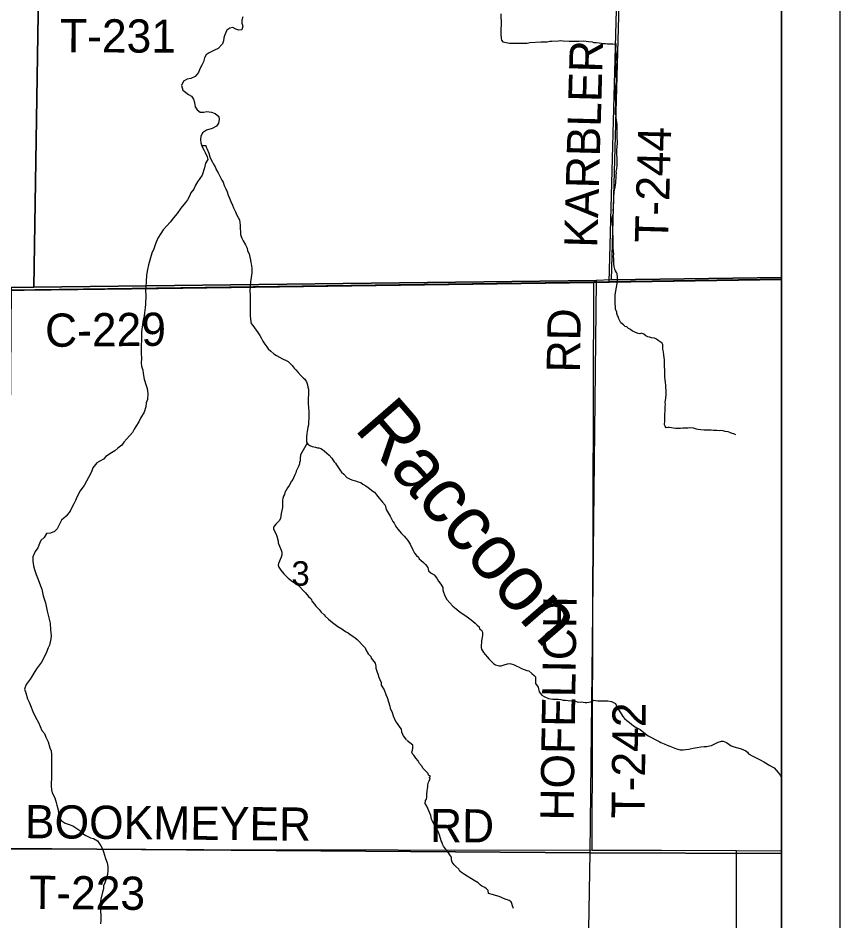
# Model space of a CAD drawing. Extents: x 36.7 to 70.7, y 0 to 22.
# Drawn here: x 44.287 to 45.693, y 18.785 to 20.33 of the extents above; entities that cross this region are included whole.
import ezdxf

# ---------------------------------------------------------------- set-up
doc = ezdxf.new("R2010")
doc.units = 0
for name, color, linetype in [('Default', 7, 'Continuous'), ('GM_X_County_Road', 7, 'Continuous'), ('GM_X_County_Road_Text', 7, 'Continuous'), ('GM_X_Minor_River', 7, 'Continuous'), ('GM_X_Minor_River_Text', 7, 'Continuous'), ('GM_X_Section', 7, 'Continuous'), ('GM_X_Section_Text', 7, 'Continuous'), ('GM_X_Township_Road', 7, 'Continuous'), ('GM_X_Township_Road_Text', 7, 'Continuous'), ('SH_Data', 7, 'Continuous')]:
    doc.layers.add(name, color=color, linetype=linetype)

msp = doc.modelspace()

# ---------------------------------------------------------------- linework, layer by layer
at = {"layer": 'Default'}
for points in [[(45.5934, 19.886), (45.5934, 20.8905), (45.3296, 20.8874), (45.3017, 19.8821)], [(45.5934, 18.9006), (45.5934, 19.886), (45.3017, 19.8821), (45.2759, 19.881), (45.2652, 18.9013)], [(45.5934, 17.918), (45.5934, 18.9006), (45.2652, 18.9013), (45.2484, 17.9213)]]:
    msp.add_lwpolyline(points, close=True, dxfattribs=at)
at = {"layer": 'GM_X_County_Road'}
for p, q in [((45.2983, 19.8779), (45.5934, 19.8826)), ((44.0658, 19.8612), (44.5269, 19.8674))]:
    msp.add_line(p, q, dxfattribs=at)
msp.add_lwpolyline([(44.5269, 19.8674), (45.2724, 19.8775), (45.2983, 19.8779)], dxfattribs=at)
at = {"layer": 'GM_X_Minor_River'}
for points in [[(45.1132, 20.3374), (45.1133, 20.3184), (45.113, 20.3112), (45.113, 20.302), (45.1138, 20.2956), (45.1142, 20.2922), (45.1165, 20.2895), (45.1279, 20.2873), (45.1336, 20.2873), (45.1458, 20.287), (45.1583, 20.2871), (45.1628, 20.2882), (45.1814, 20.2894), (45.1867, 20.2891), (45.1921, 20.2891), (45.1966, 20.2903), (45.2004, 20.2907), (45.2114, 20.2911), (45.2148, 20.2915), (45.2194, 20.2911), (45.23, 20.2904), (45.2463, 20.2905), (45.2547, 20.2909), (45.2589, 20.2906), (45.263, 20.2898), (45.2691, 20.2891), (45.2722, 20.2884), (45.276, 20.288), (45.2813, 20.2876), (45.2847, 20.2873), (45.2885, 20.2865), (45.2923, 20.2866)], [(44.6714, 20.332), (44.6694, 20.3264), (44.6694, 20.3211), (44.6712, 20.3161), (44.6696, 20.31), (44.6647, 20.3093), (44.6594, 20.3113), (44.6541, 20.314), (44.6492, 20.3125), (44.6442, 20.3096), (44.6403, 20.3013), (44.6387, 20.296), (44.6383, 20.291), (44.6364, 20.2857), (44.6294, 20.2782), (44.6226, 20.2752), (44.6138, 20.2704), (44.6084, 20.267), (44.6057, 20.2618), (44.6038, 20.2553), (44.601, 20.2493), (44.5979, 20.2429), (44.5956, 20.2368), (44.5898, 20.23), (44.5822, 20.2267), (44.5761, 20.2253), (44.5696, 20.2219), (44.5665, 20.2144), (44.5687, 20.2067), (44.5781, 20.199), (44.5834, 20.1963), (44.5871, 20.191), (44.5889, 20.1856), (44.59, 20.178), (44.593, 20.1731), (44.5986, 20.1692), (44.6047, 20.1691), (44.61, 20.1699), (44.6176, 20.169), (44.624, 20.167), (44.63, 20.1617), (44.6307, 20.1567), (44.6295, 20.1499), (44.626, 20.145), (44.6188, 20.1409), (44.6093, 20.138), (44.6024, 20.1335), (44.5993, 20.1274), (44.5988, 20.1221), (44.5995, 20.1164), (44.6017, 20.1096), (44.6047, 20.1046), (44.6069, 20.0997), (44.6103, 20.0928), (44.6113, 20.0878), (44.6075, 20.0818), (44.6055, 20.0735), (44.6015, 20.0614), (44.5977, 20.0553), (44.5938, 20.0497), (44.5904, 20.044), (44.5872, 20.0372), (44.5826, 20.0308), (44.5803, 20.0252), (44.5764, 20.0191), (44.5733, 20.0142), (44.5652, 20.0048), (44.5587, 19.9954), (44.5525, 19.9879), (44.5471, 19.9807), (44.541, 19.9743), (44.5352, 19.9679), (44.531, 19.9615)], [(45.2923, 20.2866), (45.2957, 20.2862), (45.3003, 20.2862), (45.3044, 20.2859), (45.3103, 20.2854)], [(45.3069, 19.9048), (45.3066, 19.9098), (45.3062, 19.9143), (45.3063, 19.9177), (45.3056, 19.9227), (45.3063, 19.9261), (45.3053, 19.9364), (45.3054, 19.9512), (45.3051, 19.9569), (45.3047, 19.9599), (45.3048, 19.9724), (45.3041, 19.9777), (45.3034, 19.9816), (45.3038, 19.9869), (45.3046, 19.9929), (45.3058, 19.9963), (45.3055, 20.002), (45.3059, 20.0047), (45.3059, 20.01), (45.3063, 20.0134), (45.3064, 20.0218), (45.3072, 20.0332), (45.3084, 20.0407), (45.3092, 20.0449), (45.3096, 20.0479), (45.3097, 20.051), (45.3101, 20.0567), (45.3105, 20.0616), (45.3109, 20.0646), (45.3102, 20.0677), (45.3114, 20.0722), (45.3118, 20.0775), (45.3118, 20.0825), (45.3122, 20.0855), (45.3119, 20.0916), (45.3115, 20.0954), (45.3116, 20.0984), (45.3116, 20.1037), (45.312, 20.1102), (45.3125, 20.1155), (45.3125, 20.1201), (45.3118, 20.1246), (45.3122, 20.1314), (45.3119, 20.1364), (45.3123, 20.1413), (45.312, 20.144), (45.312, 20.1478), (45.3113, 20.1527), (45.3109, 20.1558), (45.3098, 20.1596), (45.3102, 20.1626), (45.3095, 20.1653), (45.3095, 20.171), (45.3096, 20.1854), (45.3093, 20.1926), (45.3094, 20.2002), (45.309, 20.2048), (45.3091, 20.2089), (45.3107, 20.2211), (45.3107, 20.2268), (45.3104, 20.2298), (45.3105, 20.237), (45.3101, 20.2427), (45.3102, 20.2465), (45.3106, 20.2503), (45.3098, 20.2552), (45.3103, 20.2583), (45.3107, 20.2621), (45.3107, 20.2689), (45.3104, 20.2723), (45.31, 20.2765), (45.3101, 20.283), (45.3105, 20.2864)], [(44.6009, 20.1121), (44.608, 20.112), (44.6088, 20.1089), (44.6103, 20.1059), (44.613, 20.0991), (44.6149, 20.0926), (44.6172, 20.0873), (44.6195, 20.0835), (44.621, 20.0801), (44.6241, 20.0752), (44.6264, 20.0699), (44.6291, 20.065), (44.6314, 20.0608), (44.6333, 20.057), (44.6356, 20.0528), (44.6375, 20.049), (44.6395, 20.0437), (44.6421, 20.0377), (44.6444, 20.0327), (44.6464, 20.027), (44.6487, 20.0217), (44.651, 20.0161), (44.6537, 20.01), (44.6556, 20.0051), (44.6571, 20.0017), (44.659, 19.9982), (44.6613, 19.9929), (44.6636, 19.9888), (44.6656, 19.9846), (44.6663, 19.98), (44.6668, 19.9755), (44.6668, 19.9694), (44.6672, 19.9649), (44.6676, 19.9595), (44.6684, 19.9565), (44.6695, 19.9531), (44.6722, 19.9489), (44.676, 19.9421), (44.6787, 19.9364), (44.6791, 19.9319), (44.6822, 19.9266), (44.6826, 19.9239), (44.6837, 19.9186), (44.6853, 19.9121), (44.6857, 19.9091), (44.6861, 19.9064), (44.6865, 19.9011), (44.6869, 19.8985), (44.6869, 19.8943), (44.6858, 19.8863), (44.6847, 19.8787), (44.684, 19.8703), (44.6836, 19.8639), (44.6841, 19.8551), (44.6837, 19.8513), (44.6837, 19.8479), (44.6841, 19.843), (44.6841, 19.8396), (44.6838, 19.8289), (44.6839, 19.8206), (44.685, 19.8103), (44.6854, 19.8073), (44.6885, 19.8039), (44.6916, 19.7997), (44.6969, 19.7921), (44.7003, 19.7868), (44.7026, 19.7827), (44.7053, 19.7774), (44.7088, 19.7721), (44.7122, 19.7675), (44.7149, 19.7641), (44.7191, 19.76), (44.7244, 19.7554), (44.729, 19.7524), (44.7343, 19.7498), (44.7393, 19.7471), (44.7454, 19.7441), (44.7488, 19.7423), (44.7526, 19.7389), (44.7556, 19.7354), (44.7591, 19.7309), (44.7621, 19.7279), (44.766, 19.7237), (44.7705, 19.7184), (44.7744, 19.7146), (44.7774, 19.712), (44.7801, 19.7078), (44.782, 19.7025), (44.7824, 19.6983), (44.7836, 19.6949), (44.7836, 19.6858), (44.7829, 19.6794), (44.7829, 19.6748), (44.7833, 19.6702), (44.7837, 19.6638), (44.7841, 19.657), (44.7842, 19.644), (44.7838, 19.6395), (44.7835, 19.6368), (44.7835, 19.6342), (44.7828, 19.63)], [(44.531, 19.9615), (44.526, 19.9532), (44.5217, 19.9438), (44.5189, 19.9351), (44.5154, 19.9279), (44.5134, 19.9196), (44.5099, 19.9075), (44.5079, 19.8995), (44.5067, 19.89), (44.5058, 19.8794), (44.5053, 19.8699), (44.5048, 19.862), (44.5051, 19.857), (44.5051, 19.8506), (44.5046, 19.8457), (44.5046, 19.8396), (44.5041, 19.8346), (44.5029, 19.8256), (44.5025, 19.8206), (44.5016, 19.8157), (44.5004, 19.8108), (44.4996, 19.8043), (44.4984, 19.7983), (44.4979, 19.7918), (44.4975, 19.7565), (44.4978, 19.7474), (44.4974, 19.7402), (44.4981, 19.7345), (44.4999, 19.7273), (44.5009, 19.7216), (44.5027, 19.712), (44.506, 19.701), (44.5075, 19.6961), (44.5085, 19.6873), (44.508, 19.6771), (44.5061, 19.6714), (44.5052, 19.665), (44.5025, 19.6559), (44.4963, 19.6453), (44.4932, 19.6393), (44.4882, 19.6313), (44.4854, 19.6264), (44.4823, 19.6208), (44.4727, 19.6099), (44.4677, 19.6042), (44.4643, 19.599), (44.4574, 19.5941), (44.452, 19.5892), (44.4467, 19.5859), (44.4371, 19.5799), (44.4329, 19.575), (44.4268, 19.572), (44.4214, 19.5687), (44.4145, 19.5604), (44.4126, 19.5551), (44.4106, 19.5502), (44.404, 19.5377), (44.3997, 19.5302), (44.3921, 19.5204), (44.3901, 19.5151), (44.3874, 19.5102), (44.385, 19.5045), (44.3819, 19.4985), (44.3785, 19.4924), (44.3757, 19.4864), (44.3692, 19.4774), (44.3611, 19.4706), (44.3565, 19.4619), (44.3538, 19.4559), (44.3488, 19.4514), (44.3419, 19.4488), (44.3355, 19.4481), (44.3312, 19.4413), (44.3258, 19.4361), (44.3235, 19.4308), (44.3204, 19.4236), (44.3158, 19.4172), (44.3119, 19.4081), (44.3118, 19.4005), (44.3128, 19.3926), (44.315, 19.3865), (44.3176, 19.3781), (44.3209, 19.3693), (44.3253, 19.3586), (44.3272, 19.3525), (44.3297, 19.3415), (44.3333, 19.3293), (44.3362, 19.3152), (44.3391, 19.3038), (44.3413, 19.2943), (44.3423, 19.2833), (44.3433, 19.273), (44.3425, 19.2677), (44.3405, 19.2571), (44.3382, 19.2522), (44.3354, 19.2447), (44.3323, 19.2386), (44.3265, 19.2277), (44.318, 19.2164), (44.3138, 19.2088), (44.3103, 19.2035)], [(45.515, 19.6171), (45.5116, 19.6183), (45.5089, 19.619), (45.5048, 19.621), (45.5021, 19.6218), (45.4968, 19.6226), (45.4934, 19.6237), (45.4896, 19.6245), (45.4866, 19.6234), (45.4828, 19.6242), (45.4768, 19.6243), (45.473, 19.6247), (45.4684, 19.6251), (45.4608, 19.6248), (45.4555, 19.6252), (45.4506, 19.626), (45.4479, 19.6264), (45.443, 19.628), (45.4373, 19.6288), (45.4328, 19.6284), (45.4301, 19.6281), (45.4244, 19.6281), (45.4207, 19.6278), (45.4161, 19.6275), (45.4127, 19.6279), (45.4081, 19.6283), (45.4051, 19.6287), (45.4013, 19.6291), (45.3987, 19.6291), (45.396, 19.6288), (45.3941, 19.6314), (45.393, 19.6341), (45.3935, 19.6409), (45.3935, 19.6497), (45.3944, 19.6603), (45.3944, 19.6656), (45.3948, 19.6686), (45.3945, 19.6721), (45.3953, 19.6797), (45.3957, 19.6861), (45.3958, 19.6895), (45.3958, 19.6933), (45.3954, 19.6971), (45.3955, 19.7021), (45.3948, 19.7062), (45.394, 19.7116), (45.3937, 19.7154), (45.3934, 19.7199), (45.3934, 19.729), (45.3931, 19.7321), (45.3932, 19.7454), (45.3921, 19.753), (45.3914, 19.759), (45.3903, 19.7632), (45.3903, 19.7674), (45.39, 19.7708), (45.3889, 19.7735), (45.3855, 19.7762), (45.3825, 19.7781), (45.3795, 19.7804), (45.3761, 19.7823), (45.3708, 19.7831), (45.3677, 19.7839), (45.3643, 19.7843), (45.3609, 19.7863), (45.3575, 19.789), (45.3538, 19.7909), (45.3507, 19.7898), (45.3481, 19.7902), (45.3435, 19.7917), (45.3409, 19.7929), (45.3382, 19.7944), (45.3348, 19.7971), (45.3314, 19.7987), (45.3284, 19.8014), (45.3258, 19.8025), (45.3232, 19.8052), (45.3186, 19.8087), (45.3164, 19.8117), (45.3149, 19.8155), (45.3142, 19.8182), (45.3127, 19.8212), (45.3116, 19.8243), (45.3116, 19.8269), (45.3093, 19.8319), (45.309, 19.8365), (45.3087, 19.8403), (45.3087, 19.8456), (45.3084, 19.852), (45.3088, 19.8566), (45.3092, 19.8592), (45.3104, 19.8664), (45.3116, 19.8721), (45.312, 19.8763), (45.3124, 19.8816), (45.3125, 19.8873), (45.3121, 19.8922), (45.311, 19.8949), (45.3095, 19.8976), (45.308, 19.9006), (45.3069, 19.9048)], [(44.7828, 19.63), (44.7813, 19.6224), (44.7809, 19.6189), (44.7802, 19.6129), (44.7802, 19.6068), (44.7806, 19.6041), (44.7825, 19.6007), (44.7863, 19.5988), (44.7898, 19.597), (44.7958, 19.5958), (44.7989, 19.5947), (44.8015, 19.5944), (44.8046, 19.5932), (44.8076, 19.5917), (44.8107, 19.5895), (44.8152, 19.5853), (44.8194, 19.5819), (44.8236, 19.577), (44.8255, 19.5743), (44.8278, 19.5709), (44.8298, 19.5683), (44.8317, 19.5653), (44.8386, 19.5554), (44.8405, 19.5528), (44.8443, 19.5494), (44.8496, 19.5441), (44.8549, 19.541), (44.8599, 19.5392), (44.8641, 19.5381), (44.869, 19.5366), (44.8732, 19.5351), (44.877, 19.5324), (44.8816, 19.5298), (44.8861, 19.5268), (44.8938, 19.5207), (44.8968, 19.5185), (44.9003, 19.5143), (44.9048, 19.5082), (44.9102, 19.5014), (44.9148, 19.4965), (44.9167, 19.4889), (44.9236, 19.4776), (44.9282, 19.4688), (44.9305, 19.4658), (44.932, 19.4624), (44.9343, 19.4582), (44.937, 19.4548), (44.9397, 19.4518), (44.9431, 19.448), (44.9473, 19.4435), (44.9507, 19.4397), (44.9538, 19.4359), (44.958, 19.4299), (44.9626, 19.42), (44.9653, 19.4143), (44.9687, 19.4102), (44.9718, 19.4075), (44.9729, 19.4045), (44.976, 19.4022), (44.9806, 19.3981), (44.984, 19.3947), (44.9882, 19.3897), (44.9894, 19.384), (44.9939, 19.3803), (44.9989, 19.3773), (45.0012, 19.3746), (45.0038, 19.3704), (45.0061, 19.3667), (45.0103, 19.3614), (45.0134, 19.3553), (45.0134, 19.3515), (45.0146, 19.3477), (45.0165, 19.3428), (45.0181, 19.339), (45.0204, 19.3348), (45.0257, 19.3295), (45.031, 19.3238), (45.0364, 19.3189), (45.0436, 19.3133), (45.0531, 19.3069), (45.0623, 19.3001), (45.0688, 19.2948), (45.0726, 19.291), (45.0756, 19.2884), (45.0764, 19.2849), (45.0798, 19.2827), (45.0817, 19.2793), (45.0814, 19.2732), (45.0807, 19.2679), (45.0799, 19.2637), (45.0796, 19.261), (45.0792, 19.2576), (45.0792, 19.253), (45.08, 19.25), (45.0831, 19.2443), (45.0861, 19.2409), (45.0899, 19.2364), (45.0926, 19.2334), (45.096, 19.23), (45.1006, 19.2258), (45.104, 19.2235)], [(44.7815, 19.6025), (44.7701, 19.5825), (44.7696, 19.5761), (44.7692, 19.5723), (44.7684, 19.5697), (44.7683, 19.567), (44.7667, 19.5629), (44.7624, 19.5546), (44.7619, 19.5519), (44.7603, 19.5482), (44.7571, 19.5403), (44.7548, 19.5377), (44.7509, 19.5302), (44.7478, 19.5264), (44.7458, 19.5219), (44.7434, 19.5182), (44.7426, 19.5148), (44.741, 19.5118), (44.7398, 19.508), (44.7394, 19.5054), (44.7392, 19.4989), (44.7395, 19.4951), (44.7391, 19.4925), (44.7383, 19.4876), (44.737, 19.4823), (44.7357, 19.4739), (44.7337, 19.4698), (44.7306, 19.4668), (44.7279, 19.4642), (44.7256, 19.4613), (44.724, 19.4586), (44.7236, 19.4552), (44.7276, 19.4479), (44.7298, 19.4433), (44.7319, 19.4349), (44.7318, 19.4323), (44.7343, 19.4262), (44.7368, 19.4197), (44.7379, 19.4159), (44.7382, 19.4113), (44.737, 19.4075), (44.735, 19.4034), (44.7342, 19.4008), (44.7326, 19.3966), (44.7321, 19.394), (44.7328, 19.3902), (44.7365, 19.3852), (44.7417, 19.379), (44.7487, 19.3716), (44.7565, 19.3658), (44.7655, 19.3603), (44.7788, 19.3464), (44.784, 19.3402), (44.7885, 19.336), (44.7903, 19.3314), (44.7943, 19.3271), (44.7965, 19.3237), (44.8021, 19.3178), (44.8054, 19.3136), (44.8106, 19.309), (44.8121, 19.3063), (44.818, 19.3012), (44.8247, 19.2958), (44.8337, 19.2891), (44.8408, 19.2848), (44.8453, 19.2817), (44.8483, 19.2798), (44.8516, 19.2778), (44.8553, 19.2751), (44.8598, 19.2723), (44.8639, 19.2692), (44.8673, 19.2665), (44.8706, 19.263), (44.8762, 19.2568), (44.8806, 19.2522), (44.8817, 19.2491), (44.8861, 19.2422), (44.8905, 19.2376), (44.8912, 19.2349), (44.8979, 19.226), (44.8986, 19.2234), (44.8989, 19.2207), (44.8988, 19.2177), (44.9006, 19.2123), (44.9031, 19.2062), (44.9035, 19.2035), (44.9082, 19.1932), (44.9084, 19.1886), (44.9132, 19.1802), (44.9164, 19.1726), (44.9186, 19.1672), (44.9232, 19.1523), (44.9235, 19.1489), (44.9268, 19.1416), (44.9289, 19.1359), (44.9318, 19.129), (44.934, 19.1252), (44.9369, 19.1209), (44.9399, 19.1159), (44.9421, 19.1129), (44.9427, 19.1087)], [(45.104, 19.2235), (45.1078, 19.222), (45.1105, 19.2213), (45.1135, 19.2217), (45.1188, 19.2232), (45.1245, 19.2252), (45.1279, 19.2255), (45.1306, 19.2248), (45.1348, 19.2237), (45.1394, 19.2218), (45.1443, 19.2192), (45.1485, 19.2169), (45.1576, 19.2135), (45.161, 19.2128), (45.166, 19.2086), (45.1698, 19.2052), (45.1721, 19.2026), (45.1725, 19.195), (45.1725, 19.1912), (45.1767, 19.1848), (45.1783, 19.1768), (45.1829, 19.1715), (45.1871, 19.1689), (45.1943, 19.1658), (45.2019, 19.1644), (45.211, 19.1644), (45.2159, 19.1641), (45.2197, 19.1629), (45.2235, 19.1626), (45.2281, 19.1622), (45.2338, 19.1615), (45.2372, 19.1611), (45.241, 19.1608), (45.2437, 19.16), (45.2467, 19.1596), (45.2505, 19.1597), (45.2539, 19.1593), (45.2573, 19.1586), (45.26, 19.1586), (45.2638, 19.1593), (45.2668, 19.1601), (45.2695, 19.1609)], [(44.3103, 19.2035), (44.3072, 19.1986), (44.3003, 19.1896), (44.2979, 19.1817), (44.2997, 19.1752), (44.3026, 19.1649), (44.3056, 19.1596), (44.3078, 19.1535), (44.3119, 19.1436), (44.3167, 19.1336), (44.3215, 19.1245), (44.3245, 19.1176), (44.3271, 19.1111), (44.3319, 19.1058), (44.3341, 19.0997), (44.3382, 19.0913), (44.3411, 19.081), (44.343, 19.076), (44.3437, 19.0696), (44.344, 19.0639), (44.3438, 19.0464), (44.3441, 19.0388), (44.3436, 19.0339), (44.3434, 19.016), (44.3437, 19.0092), (44.3452, 19.0043), (44.3496, 18.9955), (44.3518, 18.9879), (44.3529, 18.9829), (44.3551, 18.9749), (44.3558, 18.9688), (44.3561, 18.9635), (44.3602, 18.957), (44.367, 18.9524), (44.3742, 18.95), (44.3806, 18.9477), (44.387, 18.9431), (44.3922, 18.94), (44.3971, 18.9346), (44.4024, 18.9311), (44.4107, 18.9273), (44.4156, 18.9261), (44.4224, 18.9222), (44.4284, 18.9134), (44.431, 18.9084), (44.4328, 18.9031), (44.4346, 18.8974), (44.4361, 18.8921), (44.4394, 18.8844), (44.4405, 18.878), (44.4404, 18.8711), (44.4396, 18.8647), (44.4372, 18.8568), (44.4352, 18.8503), (44.4329, 18.845), (44.4328, 18.8401), (44.4312, 18.834), (44.4281, 18.8223), (44.4269, 18.8147), (44.4272, 18.8087), (44.4275, 18.8037), (44.4285, 18.7919), (44.4284, 18.7859), (44.428, 18.7802)], [(45.2689, 19.1607), (45.2718, 19.1628), (45.2748, 19.1621), (45.279, 19.1617), (45.2892, 19.1617), (45.2961, 19.1614), (45.3025, 19.1607), (45.309, 19.1573), (45.3121, 19.1497), (45.3174, 19.1421), (45.3201, 19.1376), (45.3216, 19.1349), (45.3247, 19.1315), (45.3289, 19.1281), (45.3334, 19.1243), (45.3403, 19.1191), (45.346, 19.1157), (45.3513, 19.1123), (45.3578, 19.1074), (45.3651, 19.1017), (45.3841, 19.0923), (45.3871, 19.0904), (45.3928, 19.0878), (45.3978, 19.0859), (45.4023, 19.084), (45.4077, 19.0818), (45.4138, 19.0795), (45.4198, 19.0777), (45.4248, 19.0777), (45.4293, 19.0781), (45.435, 19.0789), (45.4422, 19.0808), (45.449, 19.082), (45.4555, 19.0828), (45.4608, 19.0832), (45.4657, 19.0832), (45.4699, 19.0844), (45.4737, 19.0851), (45.4851, 19.0909), (45.4904, 19.0928), (45.4934, 19.0928), (45.4991, 19.0902), (45.5071, 19.0849), (45.5159, 19.0819), (45.5185, 19.0812), (45.5246, 19.0793), (45.5326, 19.0759), (45.5353, 19.074), (45.5368, 19.071), (45.5444, 19.0672), (45.549, 19.0646), (45.5524, 19.0627), (45.5566, 19.0608), (45.5634, 19.0571), (45.5733, 19.051), (45.5806, 19.0469), (45.5844, 19.0431), (45.5878, 19.039), (45.5909, 19.0344), (45.5934, 19.0301)], [(44.9427, 19.1087), (44.9445, 19.1045), (44.946, 19.1018), (44.9482, 19.0987), (44.9508, 19.0949)], [(45.1347, 18.8061), (45.1332, 18.8106), (45.1317, 18.8148), (45.1306, 18.8175), (45.1272, 18.8198), (45.1245, 18.821), (45.1219, 18.8217), (45.1177, 18.8233), (45.1143, 18.8252), (45.1102, 18.8268), (45.1037, 18.8284), (45.1003, 18.8299), (45.092, 18.8319), (45.0913, 18.8368), (45.0883, 18.8399), (45.0853, 18.8422), (45.0804, 18.8445), (45.0777, 18.8468), (45.074, 18.8503), (45.0676, 18.8541), (45.0506, 18.8645), (45.0457, 18.8676), (45.043, 18.8703), (45.0408, 18.8737), (45.0359, 18.8783), (45.0333, 18.881), (45.0299, 18.8856), (45.0284, 18.8894), (45.0288, 18.8939), (45.027, 18.8966), (45.0236, 18.9016), (45.0183, 18.9081), (45.0146, 18.9127), (45.0131, 18.9161), (45.0124, 18.9191), (45.0109, 18.9218), (45.0105, 18.9248), (45.0094, 18.9279), (45.0087, 18.9306), (45.0075, 18.9332), (45.006, 18.9367), (45.0031, 18.9428), (44.9997, 18.9489), (44.9978, 18.9527), (44.996, 18.9557), (44.9945, 18.9592), (44.993, 18.9652), (44.99, 18.9732), (44.9863, 18.9816), (44.9837, 18.9862), (44.9841, 18.9908), (44.9857, 18.9934), (44.9861, 18.9961), (44.9865, 19.0017), (44.9869, 19.0071), (44.9873, 19.0116), (44.9881, 19.0143), (44.9882, 19.0181), (44.9893, 19.0222), (44.9905, 19.0249), (44.992, 19.0275), (44.9909, 19.0302), (44.9924, 19.0328), (44.9894, 19.0344), (44.9883, 19.037), (44.9853, 19.0409), (44.9823, 19.0435), (44.9797, 19.0462), (44.9782, 19.0493), (44.974, 19.0546), (44.9714, 19.0588), (44.9673, 19.0638), (44.9639, 19.0684), (44.9617, 19.0711), (44.9609, 19.0737), (44.9617, 19.0771), (44.9621, 19.0802), (44.9625, 19.0828), (44.9622, 19.0855), (44.952, 19.0939)]]:
    msp.add_lwpolyline(points, dxfattribs=at)
at = {"layer": 'GM_X_Section'}
for points in [[(44.3293, 20.877), (44.3136, 19.8697), (44.2753, 19.8692), (43.3171, 19.855), (43.3259, 20.8559)], [(45.3296, 20.8874), (45.3017, 19.8821), (45.2759, 19.881), (44.3136, 19.8697), (44.3293, 20.877)], [(45.2759, 19.881), (45.2652, 18.9013), (44.2682, 18.9088), (44.2753, 19.8692), (44.3136, 19.8697)], [(45.2652, 18.9013), (45.2484, 17.9213), (44.2567, 17.9094), (44.2682, 18.9088)]]:
    msp.add_lwpolyline(points, close=True, dxfattribs=at)
at = {"layer": 'GM_X_Township_Road'}
for p, q in [((45.2983, 19.8779), (45.3122, 20.3833)), ((45.2693, 18.9059), (45.2724, 19.8775)), ((44.0087, 18.9088), (44.5054, 18.9076)), ((44.5054, 18.9076), (44.6046, 18.9074)), ((44.6046, 18.9074), (45.2693, 18.9059)), ((45.5166, 18.9055), (45.5934, 18.9052))]:
    msp.add_line(p, q, dxfattribs=at)
for points in [[(43.3189, 19.8494), (44.0245, 19.8612), (44.0656, 19.8618), (45.2722, 19.8781), (45.2981, 19.8785), (45.5934, 19.8832), (45.5934, 20.8969), (41.3748, 20.8969)], [(45.5934, 14.0969), (45.5934, 19.8832), (45.2981, 19.8785), (45.2722, 19.8781), (44.0656, 19.8618), (44.0245, 19.8612), (43.3189, 19.8494)], [(45.2693, 18.9059), (45.3881, 18.9058), (45.5166, 18.9055)], [(45.5149, 18.3335), (45.5165, 18.4864), (45.5165, 18.7604), (45.5166, 18.9055)]]:
    msp.add_lwpolyline(points, dxfattribs=at)
at = {"layer": 'SH_Data'}
for p, q in [((45.6934, 20.9969), (45.6934, 13.9969)), ((45.5934, 20.8969), (45.5934, 14.0969))]:
    msp.add_line(p, q, dxfattribs=at)

# ---------------------------------------------------------------- texts
at = {"layer": 'GM_X_County_Road_Text'}
msp.add_text('C-229', height=0.05682, rotation=0.5511, dxfattribs=at).set_placement((44.3331, 19.7673))
at = {"layer": 'GM_X_Minor_River_Text'}
msp.add_text('Raccoon', height=0.09475, rotation=310.9846, dxfattribs=at).set_placement((44.8605, 19.6269))
at = {"layer": 'GM_X_Section_Text'}
msp.add_text('3', height=0.0419, rotation=0, dxfattribs=at).set_placement((44.7546, 19.3586))
at = {"layer": 'GM_X_Township_Road_Text'}
for s, rotation, p in [('T-231', 359.7193, (44.3583, 20.2716)), ('KARBLER', 88.3806, (45.278, 19.9366)), ('T-244', 88.3152, (45.399, 19.9448)), ('RD', 89.0128, (45.2481, 19.7231)), ('HOFELICH', 89.1656, (45.2373, 18.9563)), ('T-242', 89.4386, (45.3591, 18.96)), ('BOOKMEYER', 359.4573, (44.2982, 18.9267)), ('RD', 359.5063, (44.9915, 18.92)), ('T-223', 359.4381, (44.3053, 18.8057))]:
    msp.add_text(s, height=0.05682, rotation=rotation, dxfattribs=at).set_placement(p)

doc.saveas('drawing.dxf')
